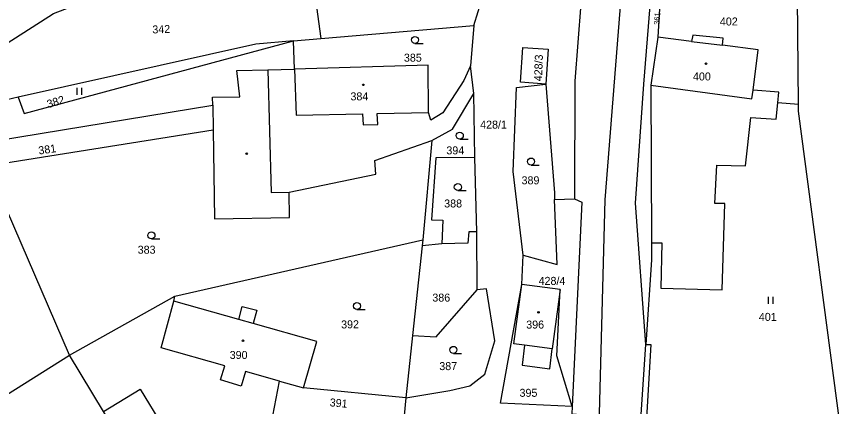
# Model space of a CAD drawing. Extents: x -520431 to -517205, y -1075927 to -1074013.
# Drawn here: x -517991.5 to -517815.8, y -1075237.3 to -1075154.3 of the extents above; entities that cross this region are included whole.
import ezdxf

# ---------------------------------------------------------------- set-up
doc = ezdxf.new("R2010")
doc.units = 0
for name, color, linetype in [('Hranice parcel', 7, 'Continuous'), ('Parcelní čísla', 7, 'Continuous'), ('Vnitřní kresba', 7, 'Continuous'), ('Značky budov', 7, 'Continuous'), ('Značky kultur', 7, 'Continuous')]:
    doc.layers.add(name, color=color, linetype=linetype)

msp = doc.modelspace()

# ---------------------------------------------------------------- linework, layer by layer
at = {"layer": 'Hranice parcel'}
for p, q in [((-517854.32, -1075143.99), (-517855.2, -1075158.75)), ((-517894.33, -1075156.23), (-517891.73, -1075147.79)), ((-517825.33, -1075173.1), (-517825.56, -1075149.12)), ((-517926.8, -1075159.01), (-517894.33, -1075156.23)), ((-517894.33, -1075156.23), (-517895.01, -1075164.81)), ((-517932.65, -1075159.51), (-517940.66, -1075160.2)), ((-517932.65, -1075159.51), (-517926.8, -1075159.01)), ((-517932.43, -1075165.53), (-517932.65, -1075159.51)), ((-517855.2, -1075158.75), (-517856.72, -1075168.96)), ((-517848.02, -1075159.65), (-517855.2, -1075158.75)), ((-517940.66, -1075160.2), (-517991.14, -1075171.54)), ((-517894.28, -1075170.69), (-517895.01, -1075164.81)), ((-517856.72, -1075168.96), (-517856.56, -1075202.48)), ((-517991.14, -1075171.54), (-517994.77, -1075172.35)), ((-517898.83, -1075178.34), (-517894.28, -1075170.69)), ((-517894.11, -1075184.35), (-517894.28, -1075170.69)), ((-518015.54, -1075183.98), (-517949.79, -1075173.23)), ((-517949.79, -1075173.23), (-517949.7, -1075178.44)), ((-517825.33, -1075173.1), (-517829.73, -1075172.69)), ((-517825.32, -1075174.45), (-517825.33, -1075173.1)), ((-517815.76, -1075246.95), (-517825.32, -1075174.45)), ((-518014.97, -1075188.83), (-517949.7, -1075178.44)), ((-517903.26, -1075180.74), (-517898.83, -1075178.34)), ((-517903.26, -1075180.74), (-517905.14, -1075201.85)), ((-517893.65, -1075200.18), (-517894.11, -1075184.35)), ((-517877.13, -1075193.29), (-517872.92, -1075193.12)), ((-517893.6, -1075212.49), (-517893.65, -1075200.18)), ((-517957.82, -1075213.82), (-517905.14, -1075201.85)), ((-517905.28, -1075203.12), (-517907.35, -1075222.25)), ((-517905.14, -1075201.85), (-517905.28, -1075203.12)), ((-517901.07, -1075202.72), (-517905.28, -1075203.12)), ((-517856.56, -1075202.48), (-517856.54, -1075206.15)), ((-517884.07, -1075211.34), (-517883.81, -1075205.12)), ((-517856.54, -1075206.15), (-517857.73, -1075224.11)), ((-517875.95, -1075212.45), (-517884.07, -1075211.34)), ((-517980.25, -1075226.41), (-517957.82, -1075213.82)), ((-517907.35, -1075222.25), (-517908.78, -1075235.51)), ((-517858.73, -1075239), (-517857.73, -1075224.11)), ((-518066.48, -1075280.79), (-517980.25, -1075226.41)), ((-517908.78, -1075235.51), (-517930.5, -1075233.39)), ((-517908.78, -1075235.51), (-517909.08, -1075239.23))]:
    msp.add_line(p, q, dxfattribs=at)
for points in [[(-517857.73, -1075224.11), (-517859.96, -1075194.04), (-517858.2, -1075168.72), (-517856.84, -1075152.04), (-517853.98, -1075133.21), (-517852.93, -1075121.19), (-517853.57, -1075105.42), (-517854.75, -1075098.5), (-517855.51, -1075092.48)], [(-517865.88, -1075128.12), (-517870.91, -1075143.31), (-517872.87, -1075168.09), (-517872.92, -1075193.12)], [(-517930.25, -1075134.53), (-517929.71, -1075138.37), (-517927.75, -1075152.25), (-517926.8, -1075159.01)], [(-517997.08, -1075162.29), (-517983.65, -1075153.73), (-517964.12, -1075146.21)], [(-517867.74, -1075245.82), (-517867.59, -1075238.79), (-517866.37, -1075193.35), (-517863, -1075150.31)], [(-517991.14, -1075171.54), (-517989.82, -1075174.96), (-517932.65, -1075159.51)], [(-517841.48, -1075160.47), (-517841.33, -1075158.95), (-517847.8, -1075158.3), (-517848.02, -1075159.65)], [(-517879.02, -1075168.71), (-517884.38, -1075168.33), (-517883.86, -1075160.91), (-517878.5, -1075161.29), (-517879.02, -1075168.71)], [(-517834.98, -1075170.05), (-517833.9, -1075161.43), (-517841.48, -1075160.47)], [(-517895.01, -1075164.81), (-517896.4, -1075167.93), (-517900.87, -1075174.86), (-517903.47, -1075176.38), (-517903.91, -1075174.77), (-517904.04, -1075164.7), (-517932.43, -1075165.53)], [(-517949.79, -1075173.23), (-517949.82, -1075171.5), (-517944.06, -1075171.43), (-517944.65, -1075165.85), (-517938.05, -1075165.66), (-517932.43, -1075165.53)], [(-517883.81, -1075205.12), (-517885.96, -1075187.33), (-517885.24, -1075169.46), (-517879.02, -1075168.71), (-517877.19, -1075191.87), (-517877.13, -1075193.29)], [(-517829.73, -1075172.69), (-517829.52, -1075170.47), (-517834.98, -1075170.05)], [(-517856.56, -1075202.48), (-517854.35, -1075202.53), (-517854.58, -1075212.13), (-517841.55, -1075212.48), (-517840.97, -1075194.12), (-517843.1, -1075194.11), (-517842.65, -1075186), (-517836.61, -1075186.14), (-517835.43, -1075175.83), (-517830.07, -1075176.22), (-517829.73, -1075172.69)], [(-517949.7, -1075178.44), (-517949.39, -1075197.43), (-517933.44, -1075197.09), (-517933.56, -1075191.72), (-517915.12, -1075187.91), (-517915.31, -1075184.98), (-517903.26, -1075180.74)], [(-517894.11, -1075184.35), (-517902.4, -1075184.42), (-517903.33, -1075197.61), (-517900.88, -1075197.66), (-517901.07, -1075202.72)], [(-517980.25, -1075226.41), (-517995.06, -1075192.19), (-518014.97, -1075188.83)], [(-517883.81, -1075205.12), (-517876.58, -1075207.1), (-517877.13, -1075193.29)], [(-517872.92, -1075193.12), (-517871.35, -1075193.86), (-517873.4, -1075237.31)], [(-517893.65, -1075200.18), (-517895.39, -1075200.14), (-517895.55, -1075202.58), (-517901.07, -1075202.72)], [(-517908.78, -1075235.51), (-517899.43, -1075233.91), (-517895.17, -1075232.95), (-517891.98, -1075230.44), (-517889.83, -1075223.37), (-517891.58, -1075212.31), (-517893.6, -1075212.49)], [(-517873.4, -1075237.31), (-517888.64, -1075236.65), (-517884.07, -1075211.34)], [(-517875.95, -1075212.45), (-517877.66, -1075225.04), (-517883.53, -1075224.28), (-517885.81, -1075223.98), (-517884.07, -1075211.34)], [(-517930.5, -1075233.39), (-517927.67, -1075223.53), (-517941.21, -1075219.7), (-517944.25, -1075218.84), (-517958.03, -1075214.95), (-517957.82, -1075213.82)], [(-517907.35, -1075222.25), (-517902.33, -1075222.51), (-517893.6, -1075212.49)], [(-517873.4, -1075237.31), (-517876.66, -1075226.54), (-517875.95, -1075212.45)], [(-517857.73, -1075224.11), (-517856.72, -1075224.11), (-517857.61, -1075239.8), (-517855.7, -1075239.95), (-517853.35, -1075240.14), (-517853.58, -1075242.85)], [(-517962.49, -1075255.83), (-517973.03, -1075238.37), (-517980.25, -1075226.41)], [(-517936.98, -1075239.29), (-517935.63, -1075231.94), (-517930.5, -1075233.39)], [(-517873.4, -1075237.31), (-517873.5, -1075238.91), (-517872.48, -1075238.96)]]:
    msp.add_lwpolyline(points, dxfattribs=at)
at = {"layer": 'Vnitřní kresba'}
for p, q in [((-517848.02, -1075159.65), (-517841.48, -1075160.47)), ((-517938.05, -1075165.66), (-517937.37, -1075191.81)), ((-517932.43, -1075165.53), (-517932.07, -1075175.34)), ((-517856.72, -1075168.96), (-517835.21, -1075171.83)), ((-517835.21, -1075171.83), (-517834.98, -1075170.05)), ((-517932.07, -1075175.34), (-517917.97, -1075175.05)), ((-517917.97, -1075175.05), (-517917.83, -1075177.38)), ((-517914.81, -1075174.99), (-517903.91, -1075174.77)), ((-517914.67, -1075177.31), (-517914.81, -1075174.99)), ((-517917.83, -1075177.38), (-517914.67, -1075177.31)), ((-517937.37, -1075191.81), (-517933.56, -1075191.72)), ((-517960.75, -1075224.82), (-517958.03, -1075214.95)), ((-517944.25, -1075218.84), (-517943.53, -1075216.06)), ((-517943.53, -1075216.06), (-517940.43, -1075216.85)), ((-517940.43, -1075216.85), (-517941.21, -1075219.7)), ((-517883.53, -1075224.28), (-517884.04, -1075228.52)), ((-517947.21, -1075228.66), (-517960.75, -1075224.82)), ((-517878.16, -1075229.32), (-517877.66, -1075225.04)), ((-517948.14, -1075231.69), (-517947.21, -1075228.66)), ((-517942.82, -1075229.9), (-517943.76, -1075232.98)), ((-517935.63, -1075231.94), (-517942.82, -1075229.9)), ((-517884.04, -1075228.52), (-517878.16, -1075229.32)), ((-517943.76, -1075232.98), (-517948.14, -1075231.69)), ((-517973.03, -1075238.37), (-517965.24, -1075233.67)), ((-517965.24, -1075233.67), (-517951.17, -1075256.42))]:
    msp.add_line(p, q, dxfattribs=at)
at = {"layer": 'Značky budov'}
for centre in [(-517844.96, -1075164.39), (-517917.77, -1075168.88), (-517942.56, -1075183.53), (-517880.56, -1075217.28), (-517943.37, -1075223.35)]:
    msp.add_circle(centre, 0.175, dxfattribs=at)
at = {"layer": 'Značky kultur'}
for p, q in [((-517906.82, -1075160.08), (-517905.07, -1075160.08)), ((-517978.62, -1075171), (-517978.62, -1075169.5)), ((-517977.62, -1075171), (-517977.62, -1075169.5)), ((-517897.29, -1075180.44), (-517895.54, -1075180.44)), ((-517882.14, -1075185.96), (-517880.39, -1075185.96)), ((-517897.7, -1075191.39), (-517895.95, -1075191.39)), ((-517962.81, -1075201.67), (-517961.06, -1075201.67)), ((-517831.67, -1075215.47), (-517831.67, -1075213.97)), ((-517830.67, -1075215.47), (-517830.67, -1075213.97)), ((-517919.14, -1075216.7), (-517917.39, -1075216.7)), ((-517898.65, -1075226.04), (-517896.9, -1075226.04))]:
    msp.add_line(p, q, dxfattribs=at)
for centre in [(-517906.82, -1075159.33), (-517897.29, -1075179.69), (-517882.14, -1075185.21), (-517897.7, -1075190.64), (-517962.81, -1075200.92), (-517919.14, -1075215.95), (-517898.65, -1075225.29)]:
    msp.add_circle(centre, 0.75, dxfattribs=at)

# ---------------------------------------------------------------- texts
at = {"layer": 'Parcelní čísla'}
for s, height, rotation, p in [('361', 1.2, 86, (-517854.86, -1075156.17)), ('342', 1.7, 2, (-517962.59, -1075157.96)), ('428/3', 1.7, 88, (-517879.82, -1075168.15)), ('382', 1.7, 17, (-517984.73, -1075173.85)), ('381', 1.7, 8, (-517986.71, -1075183.72)), ('392', 1.7, 1, (-517922.49, -1075220.73)), ('391', 1.7, 355, (-517924.99, -1075237.28))]:
    msp.add_text(s, height=height, rotation=rotation, dxfattribs=at).set_placement(p)
for s, p in [('402', (-517842.02, -1075156.25)), ('385', (-517909.16, -1075163.95)), ('400', (-517847.74, -1075167.95)), ('384', (-517920.52, -1075172.19)), ('428/1', (-517892.96, -1075178.2)), ('394', (-517900.14, -1075183.68)), ('389', (-517884.16, -1075190.05)), ('388', (-517900.6, -1075194.98)), ('383', (-517965.73, -1075204.82)), ('428/4', (-517880.54, -1075211.45)), ('386', (-517903.12, -1075215.01)), ('401', (-517833.74, -1075219.11)), ('396', (-517883.17, -1075220.75)), ('390', (-517946.18, -1075227.21)), ('387', (-517901.64, -1075229.59)), ('395', (-517884.59, -1075235.27))]:
    msp.add_text(s, height=1.7, dxfattribs=at).set_placement(p)

doc.saveas('drawing.dxf')
